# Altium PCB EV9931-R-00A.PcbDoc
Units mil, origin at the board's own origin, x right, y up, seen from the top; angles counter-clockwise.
Board outline 8500 x 5300 mil, 4 copper layers (Top Layer, MidLayer1, MidLayer2, Bottom Layer); 75 components, 37 nets, 224 pads, 548 vias.
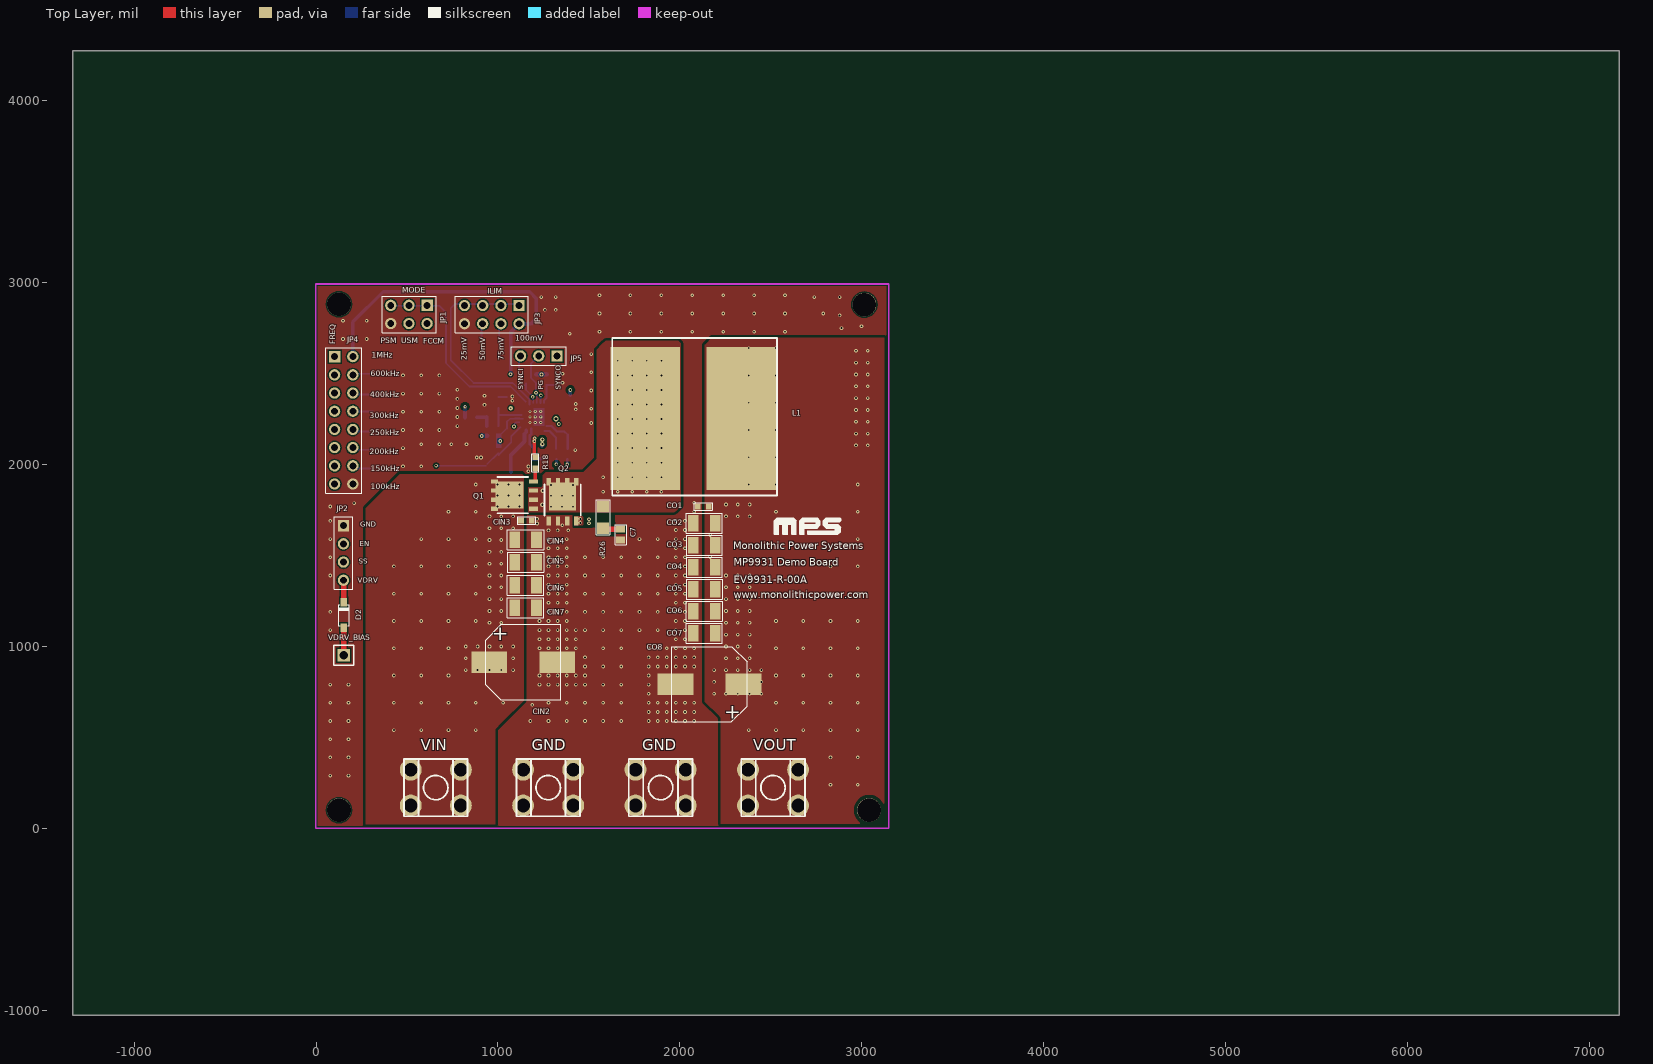
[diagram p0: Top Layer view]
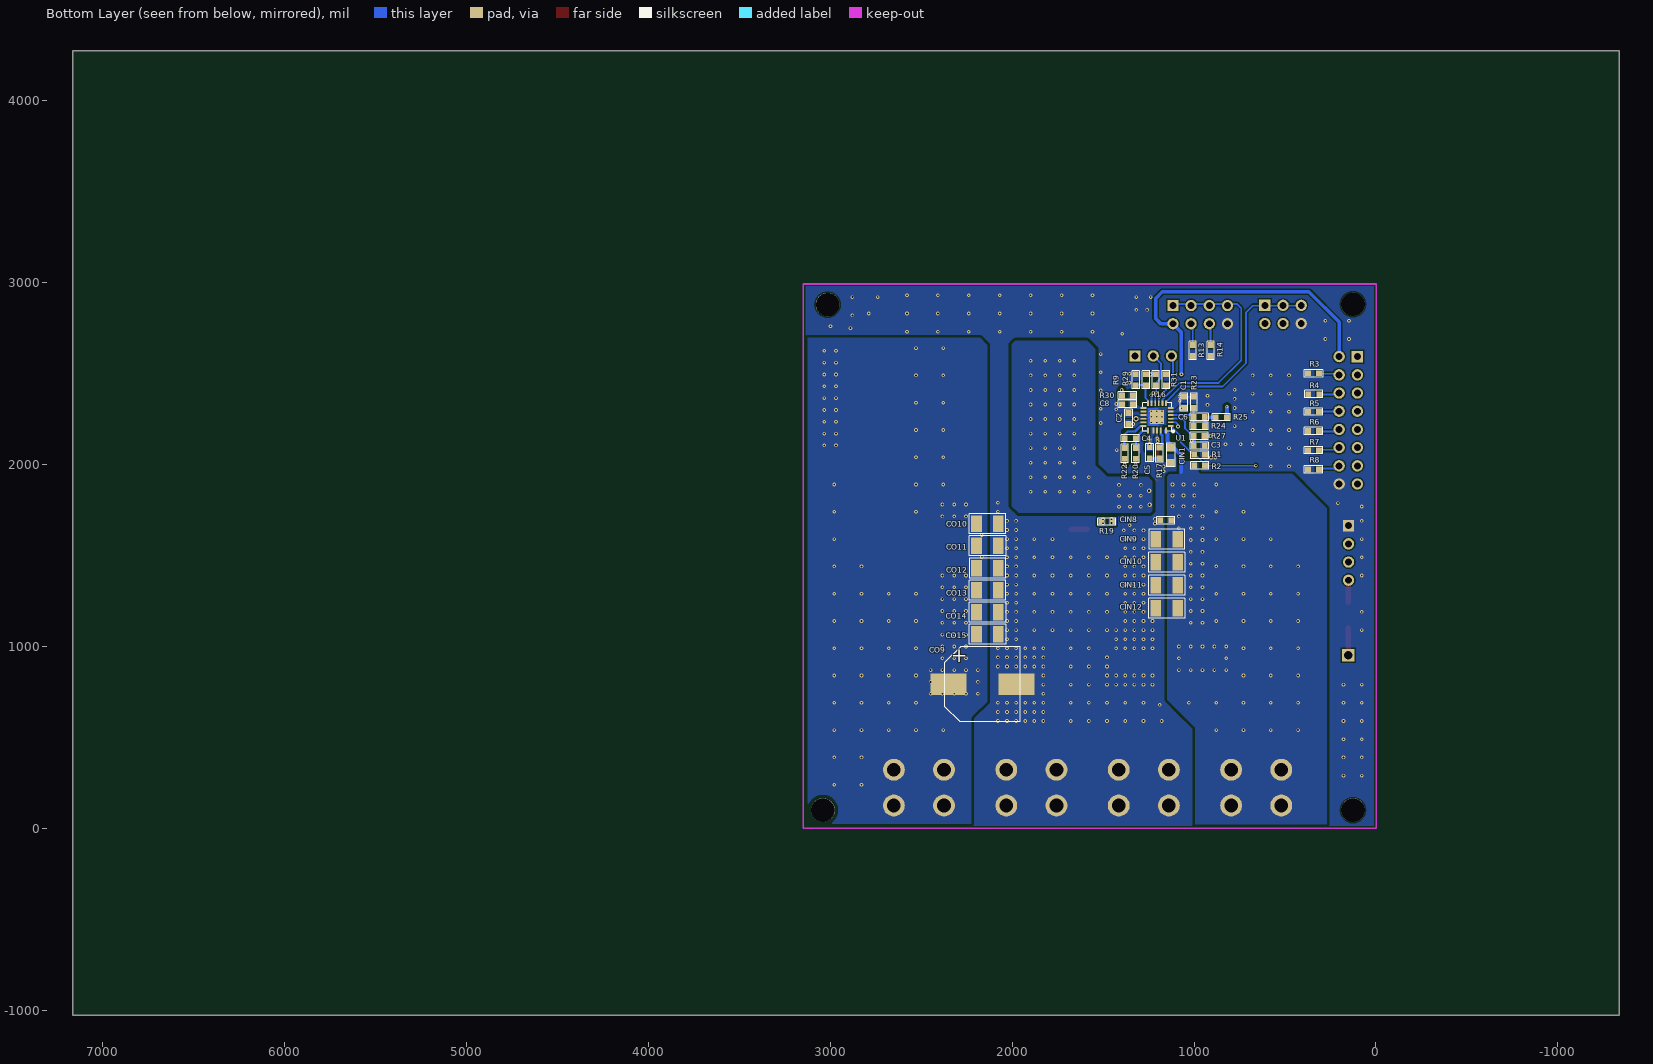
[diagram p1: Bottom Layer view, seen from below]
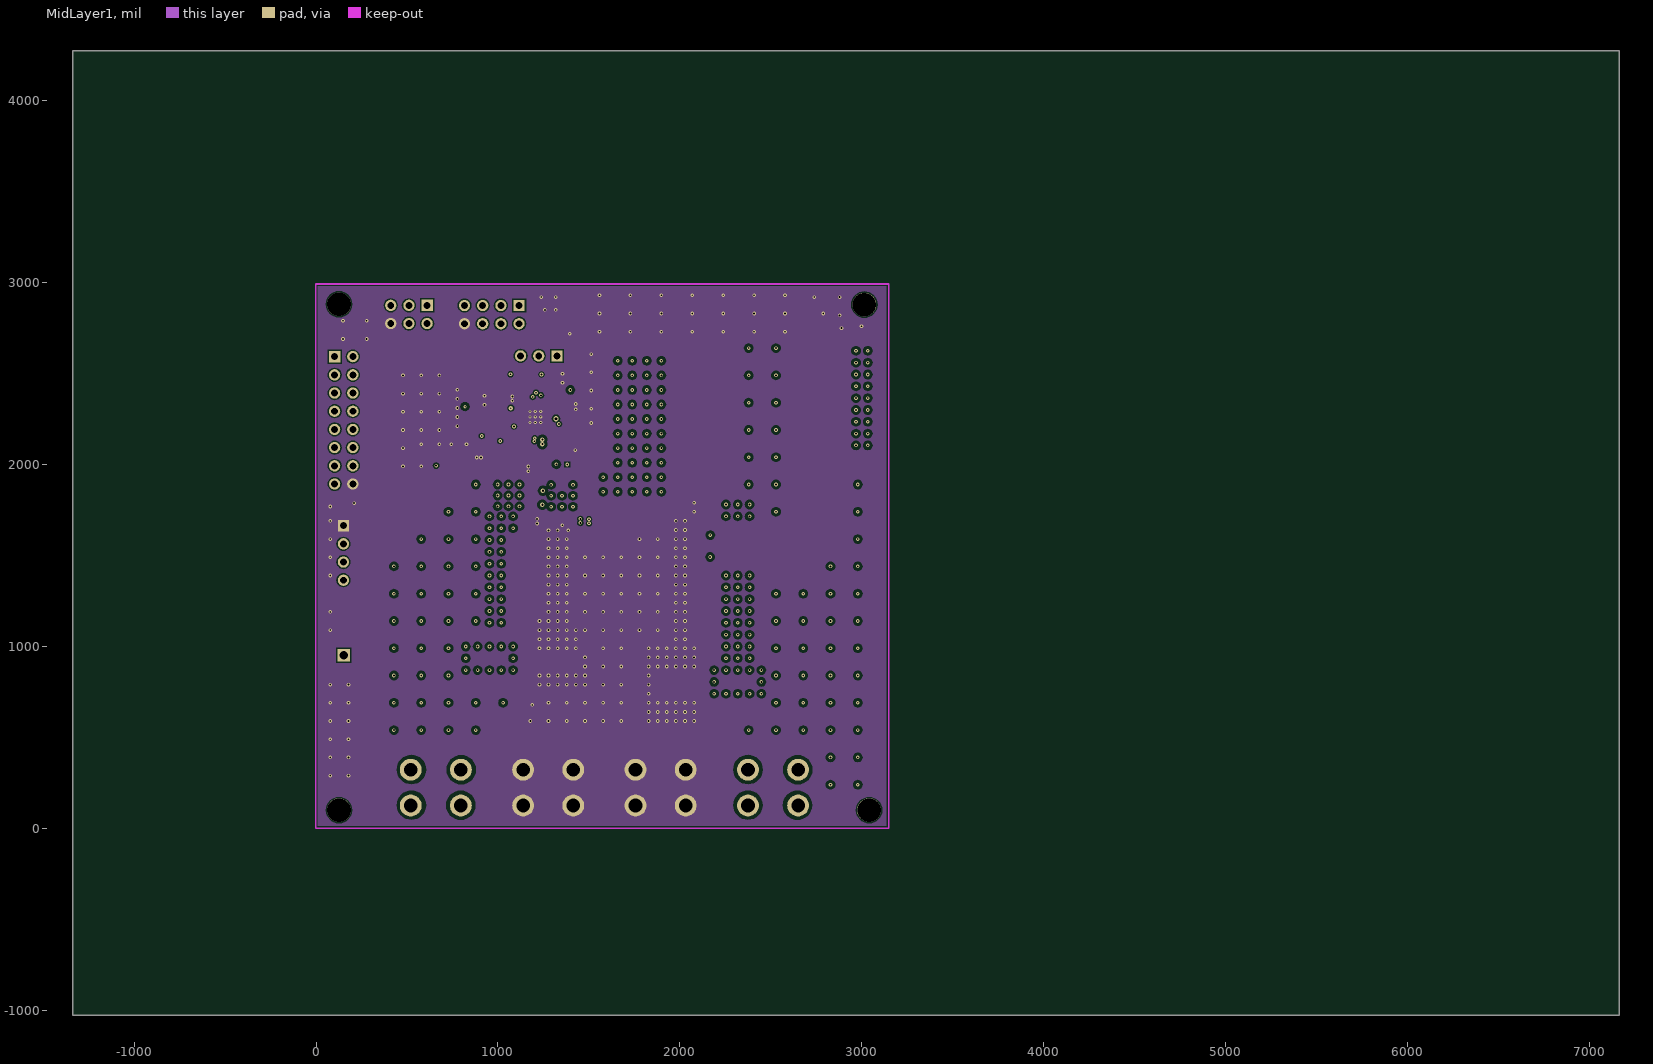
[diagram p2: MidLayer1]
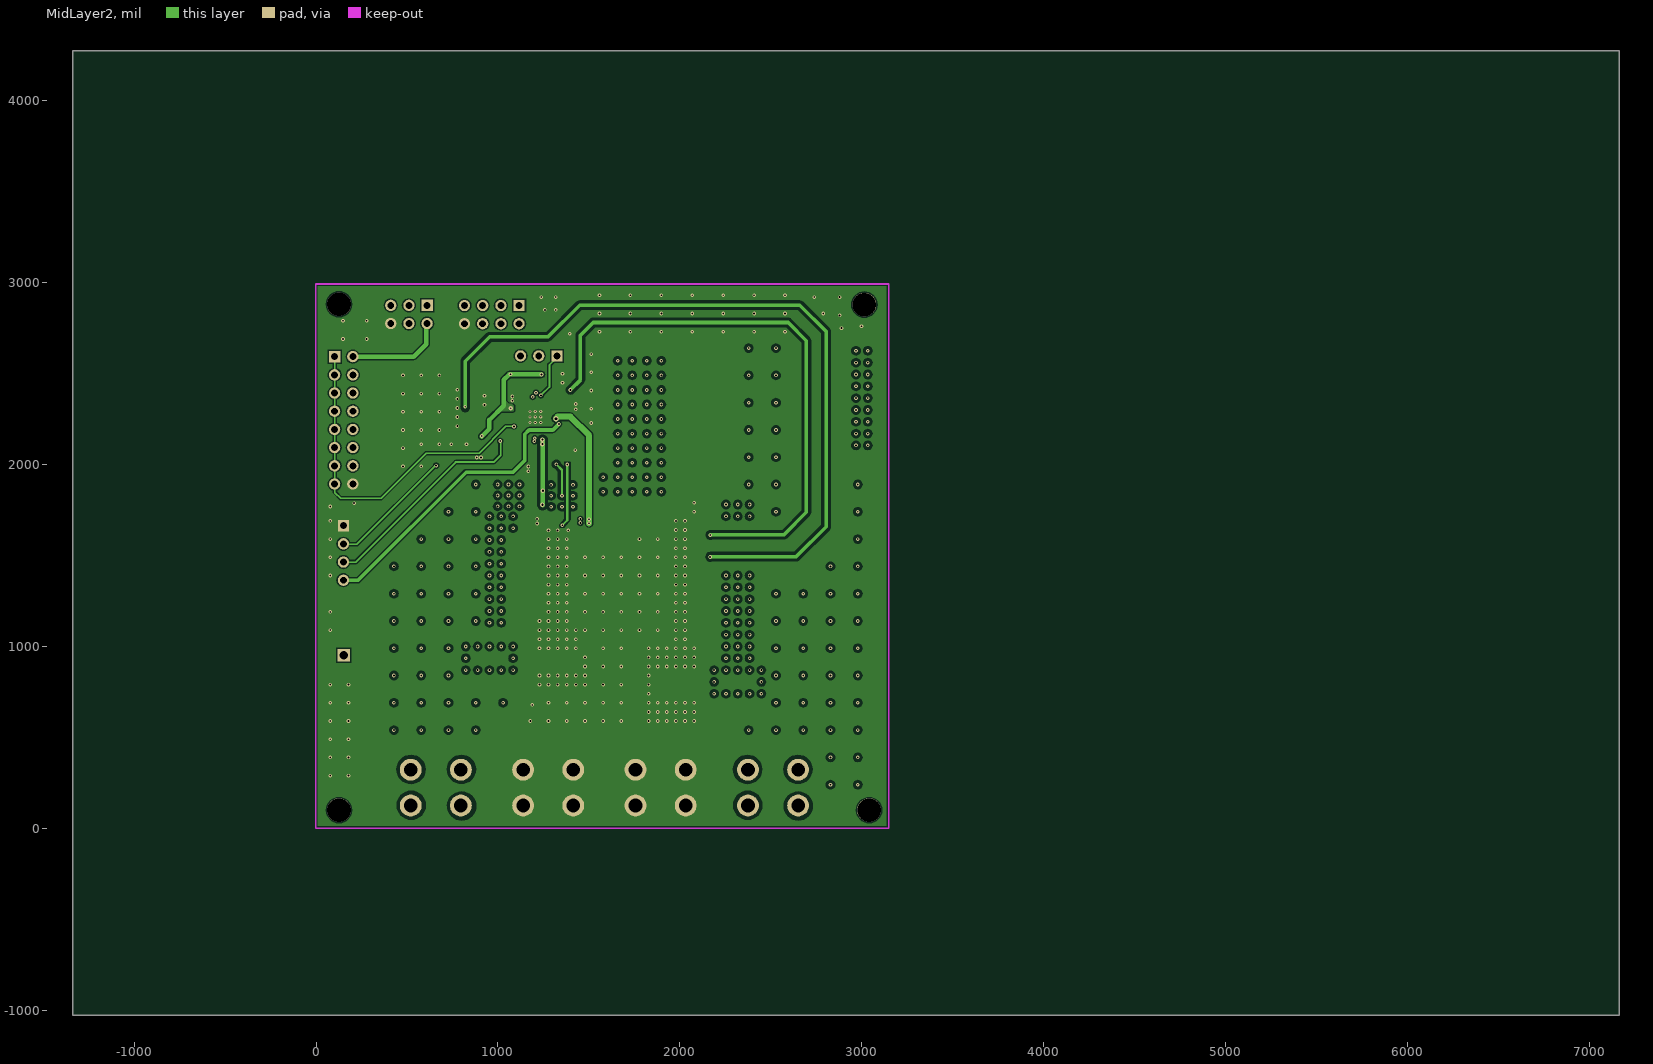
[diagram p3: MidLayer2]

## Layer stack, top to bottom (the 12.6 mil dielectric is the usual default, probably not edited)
Top Layer: signal copper 1.4
Dielectric: core 12.6, FR-4, Dk 4.8
MidLayer1: signal copper 1.4
Dielectric: prepreg 12.6, FR-4, Dk 4.8
MidLayer2: signal copper 1.4
Dielectric: core 12.6, FR-4, Dk 4.8
Bottom Layer: signal copper 1.4

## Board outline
-1337,4275 3263,4275 7163,4275 7163,3075 7163,-1025 6863,-1025 -1337,-1025

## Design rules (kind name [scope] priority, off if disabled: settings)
Clearance Clearance_4 [InNet('VOUT_1')] p1: gap=5
Clearance Clearance_3 [InNet('VOUT')] p2: gap=5
Clearance Clearance_2 [InNet('SW')] p3: gap=5
Clearance Clearance_1 [InNet('VIN')] p4: gap=5
Clearance [All] p5: gap=5
ComponentClearance [All] p1: gap=5 collisioncheckmode=3 verticalgap=5 showdistances=FALSE
FabricationTestPointUsage TestPointUsage [All] p1: valid=0 allowmultiple=FALSE
FabricationTestpoint Testpoint [All] p1: side=3 testpointundercomponent=TRUE minsize=40 maxsize=100 preferedsize=60 minholesize=0 maxholesize=40 preferedholesize=32 testpointgrid=1 allowsidetop=TRUE allowsidebottom=TRUE usegrid=TRUE gridtolerance=0.01
HoleSize [All] p1: absolutevalues=TRUE maxlimit=200 minlimit=1 maxpercent=80.000 minpercent=20.000
MinimumSolderMaskSliver [All] p1: minsoldermaskwidth=0
PlaneConnect [All] p1: planeconnectstyle=Direct reliefexpansion=20 reliefentries=4 reliefconductorwidth=10 reliefairgap=10
PolygonConnect [All] p1: connectstyle=Direct reliefconductorwidth=10 reliefentries=4 polygonreliefangle="90 Angle"
RoutingLayers [All] p1: top layer_v5=TRUE mid layer 1_v5=FALSE mid layer 2_v5=FALSE bottom layer_v5=TRUE
RoutingVias [All] p1: holewidth=12 width=25 viastyle="Through Hole" minholewidth=8 minwidth=16 maxholewidth=100 maxwidth=200
SilkToSilkClearance [All] p1: silktosilkclearance=0
SilkscreenOverComponentPads [All] p1: minsilkscreentomaskgap=0
SolderMaskExpansion [All] p1: expansion=4
Width [All] p1: maxlimit=60 minlimit=8 preferedwidth=10
19 further rules are at their usual default settings.

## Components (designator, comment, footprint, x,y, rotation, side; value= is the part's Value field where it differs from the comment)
C1 "0603" CAP/0603#1 1055.3,2372.9 r270 bottom
C2 "0603" CAP/0603#2 1365,2227 r90 bottom
C3 "0402" CAP/0603#1 941,2104 r0 bottom
C4 "0402" CAP/0603#1 1321,2145 r0 bottom
C5 "0603" CAP/0603#2 1249,2039 r90 bottom
C6 "0402" CAP/0603#1 941.22,2262.84 r0 bottom
C7 "0402" CAP0805 1680,1645 r270 top
C8 "0603" CAP/0603#1 1336,2333 r0 bottom
CIN1 "0603" CAP/0805 1128,2093 r270 bottom
CIN2 "27uF/100V" SMD_CAP10.3*10.3MM 1115,918 r0 top
CIN3 "1210" CAP/0603#1 1126,1693 r0 top
CIN4 "1210" CAP/1210 1092,1588 r0 top
CIN5 "1210" CAP/1210 1092,1463 r0 top (schematic designator CIN6)
CIN6 "1210" CAP/1210 1092,1338 r0 top
CIN7 "1210" CAP/1210 1092,1213 r0 top (schematic designator CIN3)
CIN8 "1210" CAP/0603#1 1125,1694 r0 bottom (schematic designator CIN4)
CIN9 "1210" CAP/1210 1090,1590 r0 bottom
CIN10 "1210" CAP/1210 1090,1464 r0 bottom
CIN11 "1210" CAP/1210 1090,1338 r0 bottom (schematic designator CIN12)
CIN12 "1210" CAP/1210 1090,1212 r0 bottom (schematic designator CIN11)
CO1 "1210" CAP/0603#1 2158,1770 r180 top
CO2 "1210" CAP/1210 2194,1677 r180 top
CO3 "1210" CAP/1210 2194,1556.2 r180 top
CO4 "1210" CAP/1210 2194,1435.4 r180 top
CO5 "1210" CAP/1210 2194,1314.6 r180 top
CO6 "1210" CAP/1210 2194,1193.8 r180 top
CO7 "1210" CAP/1210 2194,1073 r180 top
CO8 "NC" SMD_CAP10.3*10.3MM 2187,790 r180 top
CO9 "NC" SMD_CAP10.3*10.3MM 2187,796 r180 bottom
CO10 "1210" CAP/1210 2196,1675 r180 bottom
CO11 "1210" CAP/1210 2196,1553.4 r180 bottom
CO12 "1210" CAP/1210 2196,1431.8 r180 bottom
CO13 "1210" CAP/1210 2196,1310.2 r180 bottom
CO14 "1210" CAP/1210 2196,1188.6 r180 bottom
CO15 "1210" CAP/1210 2196,1067 r180 bottom
D2 "SOD-323" SOD-123 152,1098 r90 top
GND "KEYSTONE7697-75" KEYSTONE-7697-75 1894,225 r270 top (schematic designator GND1)
GND "KEYSTONE7697-75" KEYSTONE-7697-75 1276,225 r90 top (schematic designator GND2)
JP1 "HEADER6" "HEADER 2X3" 610.5,2876 r180 top
JP2 "HEADER 4" CONN/DIP/4PIN/2.54MM/A 150.5,1665 r270 top (schematic designator CN1)
JP3 "HEADER8P" "HEADER 2X4" 1116,2875 r180 top
JP4 "HEADER16P" HEADER2X8 102,2594 r270 top
JP5 "CONN/DIP/3PIN" CONN/3PIN/2.54MM 1324,2598 r180 top (schematic designator CN2)
L1 "MPL-AY1265-4R7" L23*22MM 1742,2270 r0 top
Q1 "DFNW8" POWERPAK/SO-8 1196,1758 r180 top (schematic designator Q1A)
Q2 "DFNW8" POWERPAK/SO-8 1280,1691 r90 top (schematic designator Q2A)
R1 "0603" RES/0603 939.22,2054 r0 bottom
R2 "0603" RES/0603 939,1996 r0 bottom
R3 "RES0603" RES/0603 373.27,2502 r180 bottom
R4 "RES0603" RES/0603 372,2388 r180 bottom
R5 "RES0603" RES/0603 373.27,2290.88 r180 bottom
R6 "RES0603" RES/0603 373.27,2185.32 r180 bottom
R7 "RES0603" RES/0603 373.27,2079.76 r180 bottom
R8 "RES0603" RES/0603 373.27,1974.2 r180 bottom
R9 "RES0603" RES/0603 1320,2497 r270 bottom
R13 "RES0603" RES/0603 1007.4,2597.73 r90 bottom
R14 "RES0603" RES/0603 907.9,2597.73 r90 bottom
R16 "0603" RES/0603 1210,2497 r270 bottom
R17 "0603" RES/0603 1190,2094 r270 bottom
R18 "0603" RES/0603 1205,2041 r270 top
R19 "0603" RES/0603 1509,1687 r180 bottom
R20 "0603" RES/0603 1321,2092 r270 bottom
R22 "0603" RES/0603 1381,2092 r270 bottom
R23 "0402" RES/0603 1002,2373 r270 bottom
R24 "0402" RES/0603 941,2213 r0 bottom
R25 "0603" RES/0603 820.22,2261.02 r0 bottom
R26 "0402" RES/1206 1578,1651 r90 top
R27 "0603" RES/0603 1002,2158 r180 bottom
R29 "RES0603" RES/0603 1264.33,2497 r270 bottom
R30 "0402" RES/0603 1396,2381 r180 bottom
R31 "RES0603" RES/0603 1154,2497 r270 bottom
U1 "MP9931" QFN23(MP9931) 1174,2312 r270 bottom
VDRV_BIAS "CONN/1MM" "header 1" 152,953 r180 top
VIN "KEYSTONE7697-75" KEYSTONE-7697-75 658,225 r270 top
VOUT "KEYSTONE7697-75" KEYSTONE-7697-75 2512,225 r270 top

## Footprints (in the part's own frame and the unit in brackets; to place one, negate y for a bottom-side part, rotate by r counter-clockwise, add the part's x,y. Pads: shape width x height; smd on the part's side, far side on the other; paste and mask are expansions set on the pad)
CAP0805 [mil]
  rect 40x50 smd: 1(-1,-6) 2(59,-6)
  silkscreen extent -26,-36 84,24, body extent -11,-31 69,19, height 50
CAP/0603#1 [mm]
  rect 0.8x0.8 smd: 1(0,0) 2(1.524,0)
  silkscreen extent -0.51,-0.51 2.03,0.51
CAP/0603#2 [mm]
  rect 0.8x0.8 smd: 1(-0.076,-0.127) 2(1.448,-0.127)
  silkscreen extent -0.58,-0.64 1.96,0.38
CAP/0805 [mm]
  rect 1x1 smd: 1(0,0) 2(2.032,0)
  silkscreen extent -0.62,-0.62 2.67,0.64
CAP/1210 [mm]
  rect 1.5x2.3 smd paste-25.4: 1(0,0) 2(3.048,0)
  silkscreen extent -1.02,-1.4 4.06,1.4
CONN/3PIN/2.54MM [mil]
  rect 62x62 hole 38: 1(0,0)
  round 62 hole 38: 2(100,0) 3(200,0)
  silkscreen extent -50,-50 250,50
CONN/DIP/4PIN/2.54MM/A [mil]
  rect 62x62 hole 38: 1(0,0)
  round 62 hole 38: 2(100,0) 3(200,0) 4(300,0)
  silkscreen extent -50,-50 350,50, body extent -50,-50 350,50, height 254
HEADER2X8 [mil]
  rect 62x62 hole 38: 1(0,0)
  round 62 hole 38: 2(0,100) 3(100,0) 4(100,100) 5(200,0) 6(200,100) 7(300,0) 8(300,100) 9(400,0) 10(400,100) 11(500,0) 12(500,100) 13(600,0) 14(600,100) 15(700,0) 16(700,100)
  silkscreen extent -50,-50 750,150
"header 1" [mm]
  rect 1.7x1.7 hole 1.194: 1(0,0)
  silkscreen extent -1.4,-1.4 1.4,1.4
"HEADER 2X3" [mil]
  rect 62x62 hole 38: 1(0,0)
  round 62 hole 38: 2(0,100) 3(100,0) 4(100,100) 5(200,0) 6(200,100)
  silkscreen extent -50,-50 248,150
"HEADER 2X4" [mil]
  rect 62x62 hole 38: 1(0,0)
  round 62 hole 38: 2(0,100) 3(100,0) 4(100,100) 5(200,0) 6(200,100) 7(300,0) 8(300,100)
  silkscreen extent -50,-50 351,150
KEYSTONE-7697-75 [mil]
  round 120 hole 75: 1(98.43,-137.8) 2(-98.43,-137.8) 3(98.43,137.8) 4(-98.43,137.8)
  silkscreen extent -158,-175 158,175
L23*22MM [mm]
  rect 9.7x20 smd mask+0.025: 1(1.698,-0.406) 2(15.142,-0.406)
  silkscreen extent -2.9,-11.18 20.09,10.82
POWERPAK/SO-8 [mil]
  rect 50x24 smd: 1(0,0) 2(0,-50) 3(0,-100) 4(0,-150)
  rect 40x24 smd: 5(215,-150) 6(215,-100) 7(215,-50) 8(215,0)
  rect 154x150 smd: 9(134,-75)
  silkscreen extent 30,-175 200,25
QFN23(MP9931) [mm]
  rect 2x2 smd mask+0.025: 0(1.255,-0.747)
  rect 0.25x0.8 smd mask+0.025: 1(2.505,1.153) 2(2.005,1.153) 3(1.505,1.153) 4(1.005,1.153) 5(0.505,1.153) 6(0.005,1.153) 13(0.005,-2.647) 14(0.505,-2.647) 15(1.005,-2.647) 16(1.505,-2.647) 17(2.005,-2.647) 18(2.505,-2.647)
  rect 0.8x0.25 smd mask+0.025: 7(-0.645,0.503) 8(-0.645,0.003) 9(-0.645,-0.497) 10(-0.645,-0.997) 11(-0.645,-1.497) 12(-0.645,-1.997) 19(3.155,-1.997) 20(3.155,-1.247) 21(3.155,-0.747) 22(3.155,-0.231) 23(3.155,0.503)
  silkscreen extent -0.75,-2.71 3.4,1.64
RES/0603 [mm]
  rect 0.8x0.8 smd: 1(0,0) 2(1.524,0)
  silkscreen extent -0.51,-0.51 2.03,0.51
RES/1206 [mil]
  rect 65x65 smd: 1(0,0) 2(120,0)
  silkscreen extent -37,-37 157,38
SMD_CAP10.3*10.3MM [mm]
  rect 5x3 smd: 1(-4.14,-0.076) 2(5.36,-0.076)
  silkscreen extent -4.64,-5.33 5.86,5.17
SOD-123 [mil]
  rect 47x37.4 smd paste-1000: 1(5,0) 2(145,0)
  silkscreen extent 16,-30 131,30

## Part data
C1 C2 C3 C4 C5 C6 C7 C8 CIN1 CIN3 CIN4 CIN5 CIN6 CIN7 CIN8 CIN9 CIN10 CIN11 CIN12 CO1 CO2 CO3 CO4 CO5 CO6 CO7 CO10 CO11 CO12 CO13 CO14 CO15: library part "Cap Semi", "Capacitor (Semiconductor SIM Model)"
CIN2 CO8 CO9: library part CAP/OD8.0P5.0, "{Description}"
D2: library part 05.0084, "Diode;75V;0.15A;"
GND GND VDRV_BIAS VIN VOUT: "{Description}"
JP5: "CONN/3PIN/2.54MM"
L1: library part TOKO106C, "TOKO106C"
Q1 Q2: library part AM4392N, "AM4392N"
R1 R2 R16 R17 R18 R19 R20 R22 R23 R24 R25 R26 R27 R30: library part 06.0150, "Film Resistor;1%"

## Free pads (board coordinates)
  round 130 hole 130: 0(126,101) 0(126,2882) 0(3014,2880) 0(3040,101)

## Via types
v1: diameter 20, hole 10, Top Layer to Bottom Layer, tented both sides, 532 vias
v2: diameter 18, hole 8, Top Layer to Bottom Layer, tented both sides, 10 vias
v3: diameter 24, hole 12, Top Layer to Bottom Layer, tented both sides, 4 vias
v4: diameter 24, hole 8, Top Layer to Bottom Layer, tented both sides, 1 vias
v5: diameter 30, hole 15, Top Layer to Bottom Layer, tented both sides, 1 vias

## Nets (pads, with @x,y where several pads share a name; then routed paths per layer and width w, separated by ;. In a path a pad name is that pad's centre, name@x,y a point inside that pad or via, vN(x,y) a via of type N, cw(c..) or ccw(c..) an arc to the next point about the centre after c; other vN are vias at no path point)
BG: R19.1 U1.16 | length 712.8
  MidLayer2 w33: v5@1318,2254 1328,2264 1398,2264 1501,2161 v1@1501,1678
  other v1: 1500,1678 1500,1700
  other v5: 1319,2253
BST: R17.1 U1.22 | length 113
  Bottom Layer w15: U1.22@1183.32,2195.9 1183.32,2168.52 1174,2159.2 1174,2115 R17.1@1194,2095
BST1: C5.1 R17.2 | length 51
  Bottom Layer w20: R17.2@1188,2034 R17.2 ; R17.2@1193,2033 C5.1@1238,2033 ; C5.1 C5.1@1248,2036
DRVH: Q1.4 R18.2 | length 67
  Top Layer w20: Q1.4@1204,1914 R18.2@1204,1981
DRVL: Q2.4 R19.2
  other v1: 1453,1680 1453,1702
EN: JP2.2 R1.2 R2.1 U1.1 | length 1261.4
  MidLayer2 w8: JP2.2@148,1562 224,1562 655.5,1993.5 v1@655.5,1997.5
  Bottom Layer w8: v1@659.5,1998.5 663.5,1998.5 667,1995 R2.1@936,1995 ; R1.2@1005.5,2049.5 1005.5,2055.5 1074,2124 1074,2156 1126,2208
  Bottom Layer w10: R2.1@941,2004 R1.2@1001,2064
  other v1: 660,1995
FB: C6.2 R23.2 R24.2 U1.4 | length 224.3
  Bottom Layer w10: R24.2@1000,2211 1002,2213 R23.2 ; C6.2@1006.94,2272.94 1040.24,2272.94 U1.4@1128.4,2272.94
FREQ: JP4.1 JP4.3 JP4.5 JP4.7 JP4.9 JP4.11 JP4.13 JP4.15 U1.2 | length 1958.8
  MidLayer2 w8: JP4.15 JP4.13 JP4.11 JP4.9 JP4.3 JP4.1 102,2598 JP4.1@105,2601 ; JP4.15@104,1892 104,1847 135,1816 357,1816 605,2064 896,2064 1043.5,2211.5 v1@1085.5,2211.5
  Bottom Layer w8: v1@1089.5,2209 1089.5,2223.2 1099.87,2233.57 U1.2@1118.42,2233.57
  other v1: 1088,2210
GND: C1.1 C2.2 C3.1 C7.2 C8.2 CIN1.2 CIN2.2 CIN3.2 CIN4.2 CIN5.2 CIN6.2 CIN7.2 CIN8.2 CIN9.2 CIN10.2 CIN11.2 CIN12.2 CO1.2 CO2.2 CO3.2 CO4.2 CO5.2 CO6.2 CO7.2 CO8.2 CO9.2 CO10.2 CO11.2 CO12.2 CO13.2 CO14.2 CO15.2 GND.1 GND.2 GND.3 GND.4 JP1.6 JP2.1 JP3.8 JP4.16 Q2.1 Q2.2 Q2.3 R1.1 R3.1 R4.1 R5.1 R6.1 R7.1 R8.1 R9.1 R13.1 R14.1 R22.2 R23.1 R31.1 U1.0 U1.6 U1.15 | length 422.2
  MidLayer2 w12: v1@1354,1668 1381,1695 v1(1381,2001)
  Bottom Layer w12: R23.1 C1.1@1048,2373 ; v1@1381,2000 v1(1381,2001) R22.2
  other v1: 78,291 178,291 78,391 178,391 78,491 178,491 78,591 178,591 1178,591 1278,591 1378,591 1478,591 1578,591 1678,591 1828,591 1878,591 1928,591 1978,591 2028,591 2078,591 1828,641 1878,641 1928,641 1978,641 2028,641 2078,641 1188,680 78,691 178,691 1278,691 1378,691 1478,691 1578,691 1678,691 1828,691 1878,691 1928,691 1978,691 2028,691 2078,691 1828,741 78,791 178,791 1228,791 1278,791 1328,791 1378,791 1428,791 1478,791 1578,791 1678,791 1828,791 1228,841 1278,841 1328,841 1378,841 1428,841 1478,841 1828,841 1478,891 1578,891 1678,891 1828,891 1878,891 1928,891 1978,891 2028,891 2078,891 1478,941 1828,941 1878,941 1928,941 1978,941 2028,941 2078,941 1228,991 1278,991 1328,991 1378,991 1428,991 1578,991 1678,991 1828,991 1878,991 1928,991 1978,991 2028,991 2078,991 1228,1041 1278,1041 1328,1041 1378,1041 1428,1041 1978,1041 2028,1041 78,1091 1228,1091 1278,1091 1328,1091 1378,1091 1428,1091 1478,1091 1578,1091 1678,1091 1778,1091 1878,1091 1978,1091 2028,1091 1228,1141 1278,1141 1328,1141 1378,1141 1978,1141 2028,1141 78,1191 1278,1191 1328,1191 1378,1191 1478,1191 1578,1191 1678,1191 1778,1191 1878,1191 1978,1191 2028,1191 1278,1241 1328,1241 1378,1241 1978,1241 2028,1241 1278,1291 1328,1291 1378,1291 1478,1291 1578,1291 1678,1291 1778,1291 1878,1291 1978,1291 2028,1291 1278,1341 1328,1341 1378,1341 1978,1341 2028,1341 78,1391 1278,1391 1328,1391 1378,1391 1478,1391 1578,1391 1678,1391 1778,1391 1878,1391 1978,1391 2028,1391 1278,1441 1328,1441 1378,1441 1978,1441 2028,1441 78,1491 1278,1491 1328,1491 1378,1491 1478,1491 1578,1491 1678,1491 1778,1491 1878,1491 1978,1491 2028,1491 1278,1541 1328,1541 1378,1541 1978,1541 2028,1541 78,1591 1278,1591 1328,1591 1378,1591 1778,1591 1878,1591 1978,1591 2028,1591 1278,1639 1328,1639 1386,1639 1978,1641 2028,1641 1354,1667 1215,1677 78,1691 1978,1691 2028,1691 1215,1702 2078,1741 78,1770 209,1789 2078,1791 1167,1964 1167,1990 478,1991 578,1991 883.36,2039.84 906.45,2039.84 1425,2080 478,2091 578,2112 678,2112 744,2112 827,2112 478,2191 578,2191 678,2191 777,2212 1513,2229 777,2262 478,2291 578,2291 678,2291 1427,2304 1513,2308 777,2312 926,2329 1427,2334 1079,2352 777,2362 1079,2375 926,2379 478,2391 578,2391 678,2391 1513,2408 777,2412 1355,2450 478,2491 578,2491 678,2491 1355,2500 1513,2508 1513,2608 148,2691 278,2691 1394,2720 1558,2731 1728,2731 1898,2731 2068,2731 2238,2731 2408,2731 2578,2731 2888,2751 2998,2761 148,2791 278,2791 2878,2821 1558,2831 1728,2831 1898,2831 2068,2831 2238,2831 2408,2831 2578,2831 2788,2831 1258,2851 1318,2851 1238,2921 1318,2921 2738,2921 2878,2921 1558,2931 1728,2931 1898,2931 2068,2931 2238,2931 2408,2931 2578,2931
  other v2: 1176,2232 1205.5,2232 1235,2232 1205.5,2262.5 1176,2262.5 1235,2262.5 1176,2293 1205.5,2293 1235,2293
ILIM: JP3.1 JP3.3 JP3.5 JP3.7 U1.8 | length 1235.9
  Bottom Layer w10: JP3.1@1128,2878 1123,2883 762,2883 740,2861 740,2575 866,2449 1081,2449 1174,2356 U1.8@1174,2330
MODE: JP1.1 JP1.3 JP1.5 U1.7 | length 1118.7
  Bottom Layer w10: JP1.5@416,2874 678,2874 714,2838 714,2559 843,2430 1070,2430 U1.7@1153,2347
NC: U1.14
NetC6_1: C6.1 R24.1 R25.2 | length 105.3
  Bottom Layer w20: R25.2@883.8,2261.7 C6.1@938.6,2261.7 ; R24.1@939,2211.48 C6.1@939,2262
NetC7_1: C7.1 R26.1 | length 88
  Top Layer w30: R26.1@1586,1646 C7.1
NetJP3_4: JP3.4 R13.2 | length 101.3
  Bottom Layer w10: R13.2@1007,2652.7 JP3.4@1007,2754
NetJP3_6: JP3.6 R14.2 | length 100.2
  Bottom Layer w10: R14.2@910,2660 JP3.6@910,2760.2
NetJP4_4: JP4.4 R3.2 | length 85.2
  Bottom Layer w10: JP4.4@209,2500 294.2,2500
NetJP4_6: JP4.6 R4.2 | length 108
  Bottom Layer w10: JP4.6@202,2386 R4.2@310,2386
NetJP4_8: JP4.8 R5.2 | length 86.5
  Bottom Layer w10: JP4.8@227.5,2292 R5.2@314,2292
NetJP4_10: JP4.10 R6.2 | length 89.3
  Bottom Layer w10: JP4.10@222.7,2183 R6.2@312,2183
NetJP4_12: JP4.12 R7.2 | length 92.2
  Bottom Layer w10: JP4.12@221.8,2082 R7.2@314,2082
NetJP4_14: JP4.14 R8.2 | length 101.1
  Bottom Layer w10: JP4.14@212.9,1979 R8.2@314,1979
PG: JP5.2 R16.2 U1.10 | length 296.5
  Bottom Layer w10: v1@1208,2398 R16.2@1208,2447 ; R16.2 1210,2448.53 1182.25,2476.28 1182.25,2557.25 JP5.2@1225,2600 ; U1.10 v1@1213.27,2392.73
  other v1: 1209,2396
RAMP: R9.2 R29.2 U1.12 | length 160.4
  Bottom Layer w10: U1.12 1252.64,2352.64 1267,2367 R29.2@1267,2435 ; R29.2@1263,2437 1263,2439 1315,2439 R9.2@1317,2437
SENSE+: C4.1 R20.1 U1.19 | length 139.9
  Bottom Layer w12: U1.19@1256,2185 1283,2185 1319,2149 R20.1@1319,2087
SENSE-: C4.2 R22.1 U1.18 | length 212.9
  Bottom Layer w12: U1.18@1268,2213 1294,2213 1324,2183 1365,2183 1383,2165 R22.1@1383,2087
SS: C3.2 JP2.3 R27.1 U1.3 | length 1444.1
  MidLayer2 w10: JP2.3@158,1464 217,1464 767,2014 976,2014 1015,2053 v1@1015,2129
  Bottom Layer w10: C3.2@1011,2100.6 R27.1@1011,2156 ; R27.1@1011,2161 1049,2199 1049,2236 1066,2253 U1.3@1137,2253 ; 1092.45,2253.25 U1.3@1118.42,2253.25
  other v1: 1012,2130
SW: C5.2 L1.1 Q1.1 Q1.2 Q1.3 Q2.5 Q2.6 Q2.7 Q2.8 Q2.9 R20.2 R26.2 U1.20 | length 579.5
  MidLayer2 w12: v1(1321,2002) 1352,1971 v1@1352,1830
  MidLayer2 w25: v3@1245,1778 v3@1245,2136
  Bottom Layer w12: v1@1321,2001 v1(1321,2002) R20.2
  Bottom Layer w20: C5.2@1240.7,2105.9 1244,2105.9 C5.2@1246.4,2105.9
  other v1: 1292,1769 1352,1769 1412,1769 1292,1829 1352,1829 1412,1829 1578,1851 1658,1851 1738,1851 1818,1851 1898,1851 1292,1889 1412,1889 1578,1931 1658,1931 1738,1931 1818,1931 1898,1931 1658,2011 1738,2011 1818,2011 1898,2011 1658,2091 1738,2091 1818,2091 1898,2091 1658,2171 1738,2171 1818,2171 1898,2171 1658,2251 1738,2251 1818,2251 1898,2251 1658,2331 1738,2331 1818,2331 1898,2331 1658,2411 1738,2411 1818,2411 1898,2411 1658,2491 1738,2491 1818,2491 1898,2491 1658,2571 1738,2571 1818,2571 1898,2571
  other v3: 1244,1780 1247,1857 1244,2113 1244,2138
SYNCI: JP5.3 R31.2 U1.9 | length 307.1
  Bottom Layer w10: JP5.3@1111,2595 1116,2590 1116,2465 1144,2437 R31.2 ; R31.2@1154,2446 R31.2 ; v1@1192.5,2372.5 1154,2411 R31.2 ; U1.9 v1@1193.59,2373.41
  other v1: 1191,2373
SYNCO: JP5.1 U1.11 | length 283.4
  MidLayer2 w10: v1(1236,2381) 1283,2428 1283,2549 JP5.1@1320,2586
  Bottom Layer w10: U1.11 v1@1234,2381
TG: R18.1 U1.21 | length 104
  Top Layer w20: R18.1@1200,2040 v1@1200,2144
  other v1: 1200,2129 1202,2145
VCC: C1.2 JP1.2 JP3.2 JP4.2 R16.1 R27.2 R29.1 U1.5 | length 3571
  MidLayer2 w25: JP4.2 537,2594 606,2663 JP1.2@606,2767 ; v1@911,2155 953,2197 953,2246 1032,2325 1032,2466 1062,2496 v1(1239,2496)
  Bottom Layer w15: v1(1069,2497) 1069,2731 JP3.2@1114,2776 ; JP3.2 1178,2775 1210,2807 1210,2914 1173,2951
  Bottom Layer w20: JP4.2 202,2784 369,2951 1173,2951 1174,2951 1211,2914 1211,2804 1181,2774 1117,2774 1070,2727 v1@1070,2495
  Bottom Layer w25: JP1.2@610.5,2773.78 JP1.2 ; v1@910,2158 R27.2@941,2158 ; R16.1 R29.1@1268,2497
  other v1: 911,2158
  other v4: 1071,2311
VDRV: C2.1 D2.2 JP2.4 U1.17 | length 1744.2
  Top Layer w30: D2.2 JP2.4@152,1368
  MidLayer2 w20: JP2.4@156,1365 231,1365 825,1959 1083,1959 1147,2023 1147,2167 1171,2191 1302,2191 v1(1335,2224)
VDRV_BIAS: D2.1 VDRV_BIAS.1 | length 156
  Top Layer w30: VDRV_BIAS.1@152,947 VDRV_BIAS.1 D2.1
VIN: CIN1.1 CIN2.1 CIN3.1 CIN4.1 CIN5.1 CIN6.1 CIN7.1 CIN8.1 CIN9.1 CIN10.1 CIN11.1 CIN12.1 Q1.5 Q1.6 Q1.7 Q1.8 Q1.9 R2.2 U1.23 VIN.1 VIN.2 VIN.3 VIN.4 | length 267.4
  Bottom Layer w20: 1071,1958 1071,2053 1146,2128 1146,2168.9 1156,2178.9 U1.23@1156,2190.19
  other v1: 428,541 578,541 728,541 878,541 428,691 578,691 728,691 878,691 1028,691 428,841 578,841 728,841 823,871 888,871 953,871 1018,871 1083,871 823,936 1083,936 428,991 578,991 728,991 823,1001 888,1001 953,1001 1018,1001 1083,1001 953,1131 1018,1131 428,1141 578,1141 728,1141 878,1141 953,1196 1018,1196 953,1261 1018,1261 428,1291 578,1291 728,1291 878,1291 953,1326 1018,1326 953,1391 1018,1391 428,1441 578,1441 728,1441 878,1441 953,1456 1018,1456 953,1521 1018,1521 953,1586 1018,1586 578,1591 728,1591 878,1591 953,1651 1018,1651 1083,1651 953,1716 1018,1716 1083,1716 728,1741 878,1741 998,1771 1058,1771 1118,1771 998,1831 1058,1831 1118,1831 878,1891 998,1891 1058,1891 1118,1891
VOUT: CO1.1 CO2.1 CO3.1 CO4.1 CO5.1 CO6.1 CO7.1 CO8.1 CO9.1 CO10.1 CO11.1 CO12.1 CO13.1 CO14.1 CO15.1 L1.2 R25.1 R30.1 VOUT.1 VOUT.2 VOUT.3 VOUT.4 | length 7438.4
  MidLayer2 w20: v2@820,2320 820,2569 954,2703 1275,2703 1449,2877 2659,2877 2804,2732 2804,1659 2640,1495 v1@2167,1495 ; v1(1398,2411) 1453,2466 1453,2712 1523,2782 2595,2782 2695,2682 2695,1738 2572,1615 v1@2168,1615
  Bottom Layer w20: R25.1@819,2259.8 R25.1 ; R25.1@819,2264 v2(819,2319) ; R30.1@1397,2382 v1@1397,2407
  other v1: 2828,241 2978,241 2828,391 2978,391 2378,541 2528,541 2678,541 2828,541 2978,541 2528,691 2678,691 2828,691 2978,691 2188,741 2253,741 2318,741 2383,741 2448,741 2188,806 2448,806 2528,841 2678,841 2828,841 2978,841 2188,871 2253,871 2318,871 2383,871 2448,871 2253,936 2318,936 2383,936 2528,991 2678,991 2828,991 2978,991 2253,1001 2318,1001 2383,1001 2253,1066 2318,1066 2383,1066 2253,1131 2318,1131 2383,1131 2528,1141 2678,1141 2828,1141 2978,1141 2253,1196 2318,1196 2383,1196 2253,1261 2318,1261 2383,1261 2528,1291 2678,1291 2828,1291 2978,1291 2253,1326 2318,1326 2383,1326 2253,1391 2318,1391 2383,1391 2828,1441 2978,1441 2166,1493 2978,1591 2167,1613 2253,1716 2318,1716 2383,1716 2528,1741 2978,1741 2253,1781 2318,1781 2383,1781 2378,1891 2528,1891 2978,1891 2378,2041 2528,2041 2968,2106 3033,2106 2968,2171 3033,2171 2378,2191 2528,2191 2968,2236 3033,2236 2968,2301 3033,2301 2378,2341 2528,2341 2968,2366 3033,2366 2968,2431 3033,2431 2378,2491 2528,2491 2968,2496 3033,2496 2968,2561 3033,2561 2968,2626 3033,2626 2378,2641 2528,2641
VOUT_1: C8.1 R30.2 U1.13
pads on no net: JP1.4

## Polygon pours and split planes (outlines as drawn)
GND on Top Layer "Top Layer-No Net" (solid, remove dead copper, pour order 42): 10.56,2998.46 3180.56,2998.46 3180.56,28.46 3170.56,18.46 3160.56,8.46 10.56,8.46 10.56,2988.46
VOUT on Top Layer "Top Layer-No Net" (solid, remove dead copper, pour order 40): 2137,2660 2137,2097 2137,698 2213,622 2225,610 2225,1 3138,1 3142,-3 3150,5 3150,2698 2176,2698 2138,2660
SW on Top Layer "Top Layer-No Net" (solid, remove dead copper, pour order 38): 1167.01,1739 1969.71,1739 1978.79,1748 2004,1773 2004,1971 2004,2667 1998.96,2672 1989.88,2681 1877.95,2681 1591.55,2681 1571.39,2661 1542.14,2632 1542.14,2436 1542.14,2032 1501.81,1992 1468.53,1959 1340.46,1959 1262.81,1959 1250.71,1947 1246.67,1943 1246.67,1905 1246.67,1885 1241.63,1880 1236.59,1875 1168.02,1875 1166,1875 1166,1740
VIN on Top Layer "Top Layer-No Net" (solid, remove dead copper, pour order 37): 1141,1913 1141,1698 1141,703 1019,581 985,547 985,3 279,3 276,6 273,9 273,1026 273,1762 357,1846 459,1948 1075,1948 1133,1948 1138,1943 1141,1940 1141,1910
DRVL on Top Layer "Top Layer-No Net" (solid, pour order 31): 1418,1716 1418,1666 1436.47,1666 1464.6,1666 1465.48,1667 1469,1671 1469,1691 1469,1712 1466.36,1715 1464.6,1717 1418,1717
SW on Bottom Layer "Top Layer-No Net" (solid, remove dead copper, pour order 26): 1963,1735 1585,1735 1241,1735 1235,1741 1229,1747 1229,1829 1229,1910 1237,1918 1252,1933 1427,1933 1478,1933 1511,1966 1542,1997 1542,2093 1542,2636 1557,2651 1587,2681 1685,2681 1983,2681 1990,2674 2002,2662 2002,2532 2002,1773 1964,1735
DRVL on Bottom Layer "Top Layer-No Net" (solid, pour order 28): 1425,1711 1425,1676.37 1425,1667.71 1426.21,1665.24 1426.82,1664 1468.12,1664 1469.34,1666.47 1469.95,1667.71 1469.95,1703.58 1470,1709 1466.3,1711
BG on Bottom Layer "Top Layer-No Net" (solid, pour order 25): 1528,1711 1497,1711 1489,1711 1487,1709 1486,1708 1486,1693 1486,1668 1489,1665 1491,1663 1519,1663 1530,1663 1531,1664 1533,1666 1533,1680 1533,1707 1529,1711
VIN on Bottom Layer "Top Layer-No Net" (solid, remove dead copper, pour order 23): 1134,1948 1090,1948 1084,1948 1082,1950 1081,1951 1081,1994 1081,2016 1076,2021 1074,2019 1009,2019 989,2019 982,2012 977,2007 977,1989 977,1960 969,1952 966,1949 704,1949 459,1949 339,1829 271,1761 271,1573 271,11 264,4 266,2 994,2 994,555 1085,646 1147,708 1147,1828 1147,1935 1135,1947
GND on Bottom Layer "Top Layer-No Net" (solid, remove dead copper, pour order 44): 20.73,2992.75 10.73,2982.75 10.73,12.75 3160.73,12.75 3170.73,2.75 3170.73,2992.75 10.73,2992.75
VOUT on Bottom Layer "Top Layer-No Net" (solid, remove dead copper, pour order 39): 2137,2660 2137,2097 2137,698 2213,622 2225,610 2225,1 3138,1 3142,-3 3150,5 3150,2698 2176,2698 2138,2660
TG on Bottom Layer "Bottom Layer-No Net 1" (solid, remove dead copper, pour order 32): 1196.95,2204.45 1196.85,2193.24 1196.85,2157.25 1196.85,2154.95 1190.85,2148.08 1186.85,2143.5 1186.85,2124.02 1193.85,2116 1213.85,2116 1220.85,2124.02 1220.85,2144.64 1210.6,2156.39 1210.65,2204.45
VCC on Bottom Layer "Bottom Layer-No Net 1" (solid, remove dead copper, pour order 34): 1146.4,2287 1078.9,2287 1075.3,2290.6 1073.2,2292.7 1053.9,2292.7 1038.6,2292.7 1037.2,2294.1 1035.6,2295.7 1035.6,2321.6 1035.6,2328.4 1037.2,2330 1040.3,2333.1 1054.6,2333.1 1070.3,2333.1 1086.8,2316.6 1104.4,2299 1146.6,2299 1146.6,2287.7 1146.2,2287.3
BG on Bottom Layer "Bottom Layer-No Net 1" (solid, remove dead copper, pour order 30): 1262.47,2248.04 1271.03,2247.97 1298.51,2247.97 1300.26,2247.97 1305.51,2243.59 1309.01,2240.68 1323.88,2240.68 1330,2245.78 1330,2260.37 1323.88,2265.48 1308.13,2265.48 1299.17,2258 1262.47,2258.04
SW on Bottom Layer "Bottom Layer-No Net 1" (solid, remove dead copper, pour order 33): 1219.2,2205.3 1219.2,2161.8 1227.4,2152.84 1227.4,2124.31 1221.7,2118.08 1221.7,2077.09 1222.7,2076 1260,2076 1265,2080 1265,2082 1264,2117.53 1263.6,2150.32 1255.4,2159.29 1247.8,2159.29 1239.1,2168.79 1239.1,2205.3
VDRV on Bottom Layer "Top Layer-No Net" (solid, remove dead copper, pour order 27): 1298,2224 1320,2202 1374,2202 1380,2208 1380,2246 1375,2251 1343,2251 1334,2242 1334,2238 1329,2233 1305,2233 1298,2240 1261,2240 1261,2224
VOUT_1 on Bottom Layer "Top Layer-No Net" (solid, remove dead copper, pour order 29): 1263,2308 1293,2308 1351,2308 1353,2309.82 1358,2314.38 1358,2347.21 1358,2396.44 1355,2399.18 1353,2401 1342,2401 1315,2401 1314,2400.09 1314,2374.56 1314,2331.71 1311,2328.97 1299,2318.03 1263,2318.03 1263,2308
GND on Bottom Layer "Top Layer-No Net" (solid, remove dead copper, pour order 35): 1252,2265 1296,2265 1299,2265 1303,2269 1304,2270 1314,2270 1332,2270 1337,2265 1338,2264 1359,2264 1379,2264 1380,2265 1381,2266 1381,2284 1381,2301 1379,2303 1377,2305 1361,2305 1321,2305 1300,2284 1299,2283 1251,2283 1246,2283 1235,2272 1235,2266 1251,2266 1252,2265
GND on Bottom Layer "Top Layer-No Net" (solid, remove dead copper, pour order 36): 1173.47,2286.17 1154,2305.64 1138.55,2305.64 1114.45,2305.64 1101.16,2318.93 1077.99,2342.1 1048.63,2342.1 1037.2,2342.1 1030.4,2348.9 1029.47,2349.83 1029.47,2375.47 1029.47,2394.33 1034.1,2398.96 1038.12,2402.98 1055.73,2402.98 1070.56,2402.98 1080.45,2393.09 1094.36,2379.18 1094.36,2364.04 1094.36,2355.39 1099.92,2349.83 1132.37,2317.38 1144.73,2317.38 1145.66,2317.38 1148.75,2314.29 1150.29,2312.75 1202.82,2312.75 1202.82,2290.19 1200.04,2287.41 1196.95,2284.32 1171.61,2284.32
GND on MidLayer2 "Top Layer-No Net" (solid, remove dead copper, pour order 43): 5.03,2990 4.81,2973.31 4.81,3.31 3134.81,3.31 3144.81,13.31 3144.81,2993.31
VCC on MidLayer2 "Top Layer-No Net" (solid, remove dead copper, pour order 24): 1011,2294 1061,2294 1084,2294 1085,2295 1087,2297 1087,2308 1087,2325 1082,2330 1078,2334 1067,2334 1059,2334 1042,2351 1041,2352 1025,2352 1025,2319 1010,2304 1010,2295
GND on MidLayer1 "Top Layer-No Net" (solid, remove dead copper, pour order 41): 6.25,2991.23 11.25,2986.23 3147.25,2986.23 3147.25,-6.77 3142.25,-1.77 1.25,-1.77 1.25,2982.23

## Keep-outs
Keep-Out Layer:
  lines w10: -2,2 -2,2994.13 3147.61,2994.13 3147.61,2 -2,2

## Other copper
Top Layer:
  pour cut-out: 1503,1653 1531,1653 1534,1650 1534,1607 1537,1604 1644,1604 1648,1608 1648,1683 1645,1686 1645,1727 1517,1727 1515,1725 1515,1662 1509,1662 1503,1656
  pour cut-out: 1409,1725 1409,1657 1414,1652 1519,1652 1523,1656 1523,1719 1529,1725 1528,1726 1410,1726
  pour cut-out: 1228,2065 1230,2063 1230,1881 1228,1883 1148,1883 1148,1947 1147,1948 1149,1950 1177,1950 1177,2059 1185,2067 1227,2067 1229,2065
MidLayer1:
  pour cut-out: 2294.05,128.69 cw(c2374.1,128.69) 2374.1,208.75 cw(c2374.1,128.69) 2454.16,128.69 cw(c2374.1,128.69) 2374.1,48.64 cw(c2374.1,128.69)
  pour cut-out: 2294.33,324.24 cw(c2374.39,324.24) 2374.39,404.3 cw(c2374.39,324.24) 2454.45,324.24 cw(c2374.39,324.24) 2374.39,244.18 cw(c2374.39,324.24)
  pour cut-out: 2565.79,128.33 cw(c2645.85,128.33) 2645.85,208.39 cw(c2645.85,128.33) 2725.9,128.33 cw(c2645.85,128.33) 2645.85,48.27 cw(c2645.85,128.33)
  pour cut-out: 2567.79,323.33 cw(c2647.85,323.33) 2647.85,403.39 cw(c2647.85,323.33) 2727.9,323.33 cw(c2647.85,323.33) 2647.85,243.27 cw(c2647.85,323.33)
  pour cut-out: 717.79,323.33 cw(c797.85,323.33) 797.85,403.39 cw(c797.85,323.33) 877.9,323.33 cw(c797.85,323.33) 797.85,243.27 cw(c797.85,323.33)
  pour cut-out: 715.79,128.33 cw(c795.85,128.33) 795.85,208.39 cw(c795.85,128.33) 875.9,128.33 cw(c795.85,128.33) 795.85,48.27 cw(c795.85,128.33)
  pour cut-out: 444.33,324.24 cw(c524.39,324.24) 524.39,404.3 cw(c524.39,324.24) 604.45,324.24 cw(c524.39,324.24) 524.39,244.18 cw(c524.39,324.24)
  pour cut-out: 444.05,128.69 cw(c524.1,128.69) 524.1,208.75 cw(c524.1,128.69) 604.16,128.69 cw(c524.1,128.69) 524.1,48.64 cw(c524.1,128.69)
MidLayer2:
  pour cut-out: 1363,1703 1338,1670 1340,1652 1365,1654 1389,1685 1399,1698 1399,2013 1395,2017 1364,2017
  pour cut-out: 2293.06,127.69 cw(c2373.11,127.69) 2373.11,207.75 cw(c2373.11,127.69) 2453.17,127.69 cw(c2373.11,127.69) 2373.11,47.64 cw(c2373.11,127.69)
  pour cut-out: 2568.79,325.33 cw(c2648.85,325.33) 2648.85,405.39 cw(c2648.85,325.33) 2728.9,325.33 cw(c2648.85,325.33) 2648.85,245.27 cw(c2648.85,325.33)
  pour cut-out: 2292.05,324.69 cw(c2372.1,324.69) 2372.1,404.75 cw(c2372.1,324.69) 2452.16,324.69 cw(c2372.1,324.69) 2372.1,244.64 cw(c2372.1,324.69)
  pour cut-out: 2570.33,123.76 cw(c2650.39,123.76) 2650.39,203.82 cw(c2650.39,123.76) 2730.45,123.76 cw(c2650.39,123.76) 2650.39,43.7 cw(c2650.39,123.76)
  pour cut-out: 720.33,123.76 cw(c800.39,123.76) 800.39,203.82 cw(c800.39,123.76) 880.45,123.76 cw(c800.39,123.76) 800.39,43.7 cw(c800.39,123.76)
  pour cut-out: 442.05,324.69 cw(c522.1,324.69) 522.1,404.75 cw(c522.1,324.69) 602.16,324.69 cw(c522.1,324.69) 522.1,244.64 cw(c522.1,324.69)
  pour cut-out: 718.79,325.33 cw(c798.85,325.33) 798.85,405.39 cw(c798.85,325.33) 878.9,325.33 cw(c798.85,325.33) 798.85,245.27 cw(c798.85,325.33)
  pour cut-out: 443.06,127.69 cw(c523.11,127.69) 523.11,207.75 cw(c523.11,127.69) 603.17,127.69 cw(c523.11,127.69) 523.11,47.64 cw(c523.11,127.69)
Bottom Layer:
  rectangle net SS: 989,2092 1020,2172
  region net GND: 1255,2213 1255,2313 1195,2313 1195,2213
  pour cut-out: 1267,2013 1150,2013 1150,2076 1218,2076 1237,2057 1263,2057 1263,2017
  pour cut-out: 959,2285 1024,2285 1024,2038 1023,2037 965,2037 965,2175 960,2180 920,2180 920,2284 918,2286 959,2286
  pour cut-out: 1403,2168 1403,2189 1386,2206 1377,2197 1326,2197 1299,2170 1299,2057 1404,2057 1406,2059 1405,2060 1405,2168
  pour cut-out: 1356,1991 1360,1987 1398,1987 1405,1994 1405,2062 1398,2069 1356,2069
  pour cut-out: 1286,2520 1191,2520 1170,2499 1170,2457 1224,2457 1233,2448 1233,2418 1218,2418 1215,2415 1215,2404 1229,2390 1257,2390 1257,2416 1259,2418 1258,2419 1245,2419 1245,2454 1244,2455 1282,2455 1288,2449 1299,2449 1299,2458 1287,2470 1287,2519
  pour cut-out: 795,2286 795,2236 796,2235 918,2235 918,2284 920,2286
Multi-Layer:
  pour cut-out: 1364,1987 1364,2017 1396,2017 1396,1987

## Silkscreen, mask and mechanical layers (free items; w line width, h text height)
Top Overlay:
  region: 2614,1617.07 2614,1672.07 2594,1672.07 2594,1617.07 2564,1617.07 2564,1672.07 2544,1672.07 2544,1617.07 2519,1617.07 2519,1692.07 2534,1707.07 2624,1707.07 2639,1692.07 2639,1617.07
  region: 2659,1668.07 2659,1692.07 2673,1707.07 2754,1707.07 2769,1692.07 2769,1668.07 2748,1668.07 2748,1687.07 2683,1687.07 2683,1668.07
  region: 2659,1617.07 2659,1672.07 2769,1672.07 2769,1667.07 2754,1652.07 2684,1652.07 2684,1617.07
  region: 2704,1637.07 2854,1637.07 2854,1652.07 2804,1652.07 2789,1667.07 2789,1692.07 2804,1707.07 2879,1707.07 2885,1702.07 2885,1692.07 2880,1687.07 2814,1687.07 2814,1672.07 2869,1672.07 2884,1657.07 2884,1632.07 2869,1617.07 2704,1617.07
  lines w4: 2624,1707.07 2639,1692.07 2639,1617.07 2614,1617.07 2614,1672.07 2594,1672.07 2594,1617.07 2564,1617.07 2564,1672.07 2544,1672.07 2544,1617.07 2519,1617.07 2519,1692.07 2534.52,1707.6 2624,1707.6 ; 2753,1707.6 2674.52,1707.6 2659,1692.07 2659,1617.07 2684,1617.07 2684,1652.07 2754,1652.07 2769,1667.07 2769,1692.07 2754,1707.07 ; 2804,1707.07 2789,1692.07 2789,1672.07 2789,1667.07 2804,1652.07 2854,1652.07 2854,1637.07 2704,1637.07 2704,1617.07 2869,1617.07 2884,1632.07 2884,1642.07 2884,1657.07 2869,1672.07 2814,1672.07 2814,1687.07 2880,1687.07 2885,1692.07 2885,1702.07 2879.47,1707.6 2804,1707.6 ; 2684,1672.07 2749,1672.07 2749,1687.07 2684,1687.07 2684,1672.07
  text "MODE" at 475,2945 h30
  text "ILIM" at 945,2941 h30
  text "100mV" at 1095,2680 h30
  text "USM" at 469,2668 h30
  text "PSM" at 356,2667 h30
  text "FCCM" at 590,2666 h30
  text "FREQ" at 105,2663 h30 r90
  text "1MHz" at 305,2589 h30
  text "25mV" at 828,2575 h30 r90
  text "50mV" at 929.67,2575 h30 r90
  text "75mV" at 1031.33,2575 h30 r90
  text "600kHz" at 301,2487 h30
  text "SYNCI" at 1140,2412 h28 r90
  text "SYNCO" at 1344.76,2412.41 h28 r90
  text "PG" at 1249,2411 h28 r90
  text "400kHz" at 297,2372 h30
  text "300kHz" at 295,2256 h30
  text "250kHz" at 297,2161 h30
  text "200kHz" at 295,2058 h30
  text "150kHz" at 301,1963 h30
  text "100kHz" at 301,1865 h30
  text "GND" at 242,1659 h28
  text "EN" at 240,1553 h28
  text "Monolithic Power Systems" at 2293,1534 h40
  text "SS" at 283,1482 h28 r180
  text "MP9931 Demo Board" at 2295,1445 h40
  text "VDRV" at 230,1351 h28
  text "EV9931-R-00A" at 2296,1348 h40
  text "www.monolithicpower.com" at 2295,1267 h40
Bottom Solder:
  rectangle: 1235,1741 1429,1914
  rectangle: 941,1736 1138,1918
Mechanical 16:
  drawing of 2311 lines, arcs and shapes, not listed
  text "3" at 4100,4725 h70
  text "4" at 6475.35,4725 h70
  text "A" at -1732,3835 h70
  text "A" at 7563,3835 h70
  text "B" at -1732,1959 h70
  text "C" at -1732,83 h70
  text "Title:" at 1721,-1440 h100
  text "T-EVL9931-QW-00A" at 2537,-1458 h100
  text "80*80mm" at 2352,-1738 h100
  text "00A" at 6702,-1739 h100
  text "Size:" at 1729,-1740 h100
  text "Engineer:" at 3401,-1740 h100
  text "Revision:" at 5685,-1740 h100
  text "Freda" at 4458,-1747 h100
  text "D" at -1732,-1789 h70
  text "D" at 7563,-1789 h70
  text "Date:" at 1729,-2040 h100
  text "Drawer:" at 3405,-2040 h100
  text "Sheet:" at 5689,-2040 h100
  text "of" at 6705,-2040 h100
  text "Technician" at 4408,-2041 h100
  text "2023/11/28" at 2224,-2044 h100
  text "1" at 6392,-2045 h100
  text "1" at 7145,-2045 h100
  text "File:" at 1733,-2340 h100
  text "1" at -634.66,-2575 h70
  text "2" at 1723.35,-2575 h70
  text "3" at 4100,-2575 h70
  text "4" at 6475.35,-2575 h70

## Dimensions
-2,2994.13 to -2,2 on Mechanical 1
3129.87,3025 to -19.74,3025 on Mechanical 1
